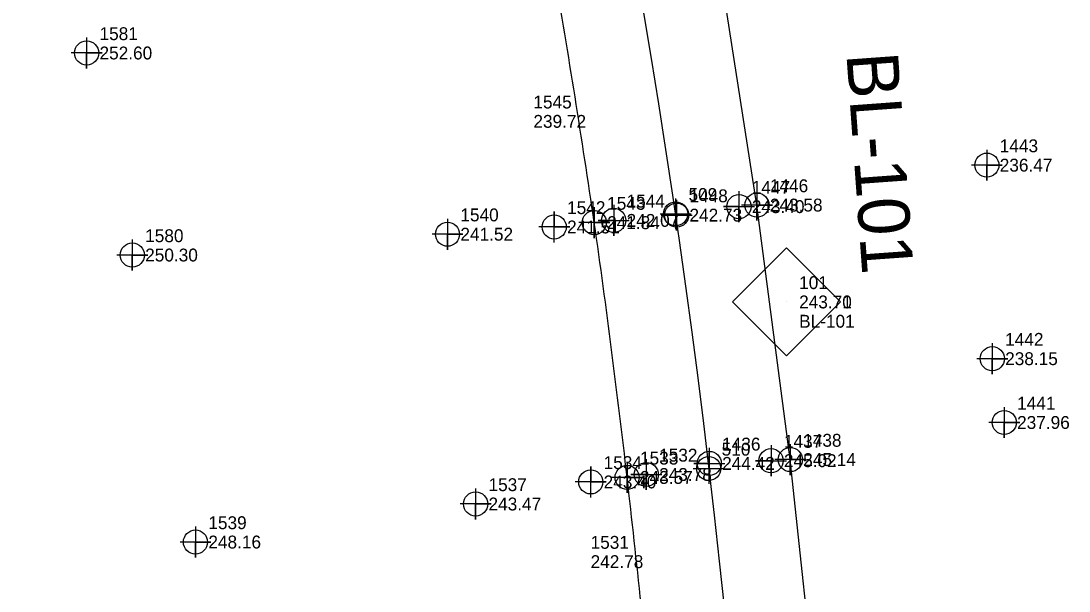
# Model space of a CAD drawing. Extents: x 2130621 to 2131998, y 642516 to 644503.
# Drawn here: x 2131091.5 to 2131294.9, y 643493.6 to 643604.3 of the extents above; entities that cross this region are included whole.
import ezdxf

# ---------------------------------------------------------------- set-up
doc = ezdxf.new("R2010")
doc.units = 0
for name, color, linetype in [('Cogo Default Point CELL', 7, 'Continuous'), ('COGO Default Point Number', 7, 'Continuous'), ('CTL Secondary Horizontal and Vertical CELL', 7, 'Continuous'), ('CTL Secondary Horizontal and Vertical Cogo Comment', 7, 'Continuous'), ('CTL Secondary Horizontal and Vertical Cogo Elevation', 7, 'Continuous'), ('CTL Secondary Horizontal and Vertical Cogo Number', 7, 'Continuous'), ('CTL Secondary Horizontal and Vertical Text', 7, 'Continuous'), ('Exist Other Culture Fence Line Cogo Elevation', 7, 'Continuous'), ('Exist Other Culture Fence Line Cogo Number', 7, 'Continuous'), ('Exist Other Culture Fence Line Cogo Point CELL', 7, 'Continuous'), ('Exist Other Culture Sign Cogo Elevation', 7, 'Continuous'), ('Exist Other Culture Sign Cogo Number', 7, 'Continuous'), ('Exist Roads EOP', 7, 'Continuous'), ('Exist Roads EOP Cogo Elevation', 7, 'Continuous'), ('Exist Roads EOP Cogo Number', 7, 'Continuous'), ('Exist Roads EOP Cogo Point CELL', 7, 'Continuous'), ('Exist Roads EOT Cogo Elevation', 7, 'Continuous'), ('Exist Roads EOT Cogo Number', 7, 'Continuous'), ('Exist Roads EOT Cogo Point CELL', 7, 'Continuous'), ('Exist Roads Soil Cogo Elevation', 7, 'Continuous'), ('Exist Roads Soil Cogo Number', 7, 'Continuous'), ('Exist Roads Soil Cogo Point CELL', 7, 'Continuous'), ('Exist Vegetation Woods Line Cogo Elevation', 7, 'Continuous'), ('Exist Vegetation Woods Line Cogo Number', 7, 'Continuous'), ('Exist Vegetation Woods Line Cogo Point CELL', 7, 'Continuous'), ('Prop Horizontal Alignment', 7, 'Continuous')]:
    doc.layers.add(name, color=color, linetype=linetype)

msp = doc.modelspace()

# ---------------------------------------------------------------- linework, layer by layer
at = {"layer": 'Cogo Default Point CELL'}
for points in [[(2131218.58, 643569.86), (2131218.58, 643566.86)], [(2131215.58, 643566.86), (2131218.58, 643566.86)], [(2131218.58, 643566.86), (2131221.58, 643566.86)], [(2131218.58, 643566.86), (2131218.58, 643563.86)], [(2131225.01, 643520.4), (2131225.01, 643517.4)], [(2131222.01, 643517.4), (2131225.01, 643517.4)], [(2131225.01, 643517.4), (2131228.01, 643517.4)], [(2131225.01, 643517.4), (2131225.01, 643514.4)]]:
    msp.add_lwpolyline(points, dxfattribs=at)
for centre in [(2131218.58, 643566.86), (2131225.01, 643517.4)]:
    msp.add_circle(centre, 2.34, dxfattribs=at)
at = {"layer": 'CTL Secondary Horizontal and Vertical CELL'}
msp.add_line((2131240.05, 643549.75), (2131240.05, 643549.75), dxfattribs=at)
msp.add_lwpolyline([(2131229.62, 643549.78), (2131240.1, 643560.27), (2131250.6, 643549.77), (2131240.12, 643539.28)], close=True, dxfattribs=at)
at = {"layer": 'Exist Other Culture Fence Line Cogo Point CELL'}
for points in [[(2131104.28, 643601.1), (2131104.28, 643595.1), (2131104.28, 643598.1), (2131107.28, 643598.1), (2131101.28, 643598.1)], [(2131113.14, 643561.86), (2131113.14, 643555.86), (2131113.14, 643558.86), (2131116.14, 643558.86), (2131110.14, 643558.86)], [(2131125.4, 643506.12), (2131125.4, 643500.12), (2131125.4, 643503.12), (2131128.4, 643503.12), (2131122.4, 643503.12)]]:
    msp.add_lwpolyline(points, dxfattribs=at)
for centre in [(2131104.28, 643598.1), (2131113.14, 643558.86), (2131125.4, 643503.12)]:
    msp.add_circle(centre, 2.34, dxfattribs=at)
at = {"layer": 'Exist Roads EOP'}
msp.add_lwpolyline([(2131264.27, 643222.56), (2131259.88, 643269.33), (2131257.02, 643319.4), (2131254.26, 643369.65), (2131250.08, 643419.42), (2131246.15, 643469.03), (2131240.84, 643519.13), (2131234.37, 643568.56), (2131226.33, 643620.18), (2131217.03, 643668.71), (2131205.62, 643717.61), (2131192.06, 643767.26), (2131177.97, 643815.09), (2131162.29, 643862.93), (2131145.36, 643910.85), (2131126.91, 643957.29), (2131112.37, 643996.12)], dxfattribs=at)
msp.add_spline([(2131166.25, 643216.7), (2131171.81, 643218.72), (2131182.37, 643223.97), (2131191.81, 643231.15), (2131200.5, 643239.7), (2131208.81, 643249.07), (2131216.07, 643259), (2131218.72, 643264.35), (2131220.54, 643270.1), (2131222.84, 643282.01), (2131224.36, 643293.92), (2131224.88, 643317.79), (2131222.06, 643367.67), (2131218.54, 643416.81), (2131214.32, 643466.35), (2131209.17, 643515.67), (2131202.79, 643565.15), (2131195.05, 643613.99), (2131186.4, 643662.48), (2131176.01, 643711.41), (2131164.62, 643759.89), (2131151.87, 643807.85), (2131137.86, 643855.41), (2131122.57, 643902.86), (2131105.96, 643949.49), (2131091.53, 643988.04)], degree=3, dxfattribs=at)
at = {"layer": 'Exist Roads EOP Cogo Point CELL'}
for points in [[(2131234.37, 643571.56), (2131234.37, 643565.56), (2131234.37, 643568.56), (2131237.37, 643568.56), (2131231.37, 643568.56)], [(2131202.79, 643568.15), (2131202.79, 643562.15), (2131202.79, 643565.15), (2131205.79, 643565.15), (2131199.79, 643565.15)], [(2131240.84, 643522.13), (2131240.84, 643516.13), (2131240.84, 643519.13), (2131243.84, 643519.13), (2131237.84, 643519.13)], [(2131209.17, 643518.67), (2131209.17, 643512.67), (2131209.17, 643515.67), (2131212.17, 643515.67), (2131206.17, 643515.67)]]:
    msp.add_lwpolyline(points, dxfattribs=at)
for centre in [(2131234.37, 643568.56), (2131202.79, 643565.15), (2131240.84, 643519.13), (2131209.17, 643515.67)]:
    msp.add_circle(centre, 2.34, dxfattribs=at)
at = {"layer": 'Exist Roads EOT Cogo Point CELL'}
for points in [[(2131230.87, 643571.26), (2131230.87, 643565.26), (2131230.87, 643568.26), (2131227.87, 643568.26), (2131233.87, 643568.26)], [(2131206.56, 643568.58), (2131206.56, 643562.58), (2131206.56, 643565.58), (2131203.56, 643565.58), (2131209.56, 643565.58)], [(2131218.77, 643569.61), (2131218.77, 643563.61), (2131218.77, 643566.61), (2131215.77, 643566.61), (2131221.77, 643566.61)], [(2131237.09, 643521.92), (2131237.09, 643515.92), (2131237.09, 643518.92), (2131234.09, 643518.92), (2131240.09, 643518.92)], [(2131225.11, 643521.39), (2131225.11, 643515.39), (2131225.11, 643518.39), (2131222.11, 643518.39), (2131228.11, 643518.39)], [(2131212.88, 643519.24), (2131212.88, 643513.24), (2131212.88, 643516.24), (2131209.88, 643516.24), (2131215.88, 643516.24)]]:
    msp.add_lwpolyline(points, dxfattribs=at)
for centre in [(2131230.87, 643568.26), (2131218.77, 643566.61), (2131206.56, 643565.58), (2131225.11, 643518.39), (2131237.09, 643518.92), (2131212.88, 643516.24)]:
    msp.add_circle(centre, 2.34, dxfattribs=at)
at = {"layer": 'Exist Roads Soil Cogo Point CELL'}
for points in [[(2131195.02, 643561.31), (2131195.02, 643567.31), (2131195.02, 643564.31), (2131198.02, 643564.31), (2131192.02, 643564.31)], [(2131202.11, 643511.79), (2131202.11, 643517.79), (2131202.11, 643514.79), (2131205.11, 643514.79), (2131199.11, 643514.79)]]:
    msp.add_lwpolyline(points, dxfattribs=at)
for centre in [(2131195.02, 643564.31), (2131202.11, 643514.79)]:
    msp.add_circle(centre, 2.34, dxfattribs=at)
at = {"layer": 'Exist Vegetation Woods Line Cogo Point CELL'}
for points in [[(2131278.98, 643579.32), (2131278.98, 643573.32), (2131278.98, 643576.32), (2131281.98, 643576.32), (2131275.98, 643576.32)], [(2131174.31, 643565.9), (2131174.31, 643559.9), (2131174.31, 643562.9), (2131177.31, 643562.9), (2131171.31, 643562.9)], [(2131280.03, 643541.73), (2131280.03, 643535.73), (2131280.03, 643538.73), (2131283.03, 643538.73), (2131277.03, 643538.73)], [(2131282.35, 643529.34), (2131282.35, 643523.34), (2131282.35, 643526.34), (2131285.35, 643526.34), (2131279.35, 643526.34)], [(2131179.77, 643513.51), (2131179.77, 643507.51), (2131179.77, 643510.51), (2131182.77, 643510.51), (2131176.77, 643510.51)]]:
    msp.add_lwpolyline(points, dxfattribs=at)
for centre in [(2131278.98, 643576.32), (2131174.31, 643562.9), (2131280.03, 643538.73), (2131282.35, 643526.34), (2131179.77, 643510.51)]:
    msp.add_circle(centre, 2.34, dxfattribs=at)
at = {"layer": 'Prop Horizontal Alignment'}
msp.add_arc((2129448.47, 643307.66), 1788.96, 4.14306, 22.49968, dxfattribs=at)

# ---------------------------------------------------------------- texts
at = {"layer": 'COGO Default Point Number'}
for s, p in [('509', (2131221.08, 643569.36)), ('510', (2131227.51, 643519.9))]:
    msp.add_text(s, height=2.5, dxfattribs=at).set_placement(p)
at = {"layer": 'CTL Secondary Horizontal and Vertical Cogo Comment'}
msp.add_text('BL-101', height=2.5, dxfattribs=at).set_placement((2131242.55, 643544.75))
msp.add_text('BL-101', height=2.5, dxfattribs=at).set_placement((2131242.55, 643544.75))
at = {"layer": 'CTL Secondary Horizontal and Vertical Cogo Elevation'}
for s in ['243.71', '243.70']:
    msp.add_text(s, height=2.5, dxfattribs=at).set_placement((2131242.55, 643548.5))
at = {"layer": 'CTL Secondary Horizontal and Vertical Cogo Number'}
msp.add_text('101', height=2.5, dxfattribs=at).set_placement((2131242.55, 643552.25))
msp.add_text('101', height=2.5, dxfattribs=at).set_placement((2131242.55, 643552.25))
at = {"layer": 'CTL Secondary Horizontal and Vertical Text'}
msp.add_text('BL-101', height=10, rotation=274.1431, dxfattribs=at).set_placement((2131251.71, 643597.91))
at = {"layer": 'Exist Other Culture Fence Line Cogo Elevation'}
for s, p in [('252.60', (2131106.78, 643596.85)), ('250.30', (2131115.64, 643557.61)), ('248.16', (2131127.9, 643501.87))]:
    msp.add_text(s, height=2.5, dxfattribs=at).set_placement(p)
at = {"layer": 'Exist Other Culture Fence Line Cogo Number'}
for s, p in [('1581', (2131106.78, 643600.6)), ('1580', (2131115.64, 643561.36)), ('1539', (2131127.9, 643505.62))]:
    msp.add_text(s, height=2.5, dxfattribs=at).set_placement(p)
at = {"layer": 'Exist Other Culture Sign Cogo Elevation'}
for s, p in [('239.72', (2131190.98, 643583.57)), ('242.78', (2131202.08, 643498.06))]:
    msp.add_text(s, height=2.5, dxfattribs=at).set_placement(p)
at = {"layer": 'Exist Other Culture Sign Cogo Number'}
for s, p in [('1545', (2131190.98, 643587.32)), ('1531', (2131202.08, 643501.81))]:
    msp.add_text(s, height=2.5, dxfattribs=at).set_placement(p)
at = {"layer": 'Exist Roads EOP Cogo Elevation'}
for s, p in [('243.58', (2131236.87, 643567.31)), ('241.84', (2131205.29, 643563.9)), ('245.14', (2131243.34, 643517.88)), ('243.57', (2131211.67, 643514.42))]:
    msp.add_text(s, height=2.5, dxfattribs=at).set_placement(p)
at = {"layer": 'Exist Roads EOP Cogo Number'}
for s, p in [('1446', (2131236.87, 643571.06)), ('1543', (2131205.29, 643567.65)), ('1438', (2131243.34, 643521.63)), ('1533', (2131211.67, 643518.17))]:
    msp.add_text(s, height=2.5, dxfattribs=at).set_placement(p)
at = {"layer": 'Exist Roads EOT Cogo Elevation'}
for s, p in [('243.40', (2131233.37, 643567.01)), ('242.07', (2131209.06, 643564.33)), ('242.73', (2131221.27, 643565.36)), ('244.42', (2131227.61, 643517.14)), ('245.02', (2131239.59, 643517.67)), ('243.78', (2131215.38, 643514.99))]:
    msp.add_text(s, height=2.5, dxfattribs=at).set_placement(p)
at = {"layer": 'Exist Roads EOT Cogo Number'}
for s, p in [('1447', (2131233.37, 643570.76)), ('1544', (2131209.06, 643568.08)), ('1448', (2131221.27, 643569.11)), ('1437', (2131239.59, 643521.42)), ('1436', (2131227.61, 643520.89)), ('1532', (2131215.38, 643518.74))]:
    msp.add_text(s, height=2.5, dxfattribs=at).set_placement(p)
at = {"layer": 'Exist Roads Soil Cogo Elevation'}
for s, p in [('241.51', (2131197.52, 643563.06)), ('243.40', (2131204.61, 643513.54))]:
    msp.add_text(s, height=2.5, dxfattribs=at).set_placement(p)
at = {"layer": 'Exist Roads Soil Cogo Number'}
for s, p in [('1542', (2131197.52, 643566.81)), ('1534', (2131204.61, 643517.29))]:
    msp.add_text(s, height=2.5, dxfattribs=at).set_placement(p)
at = {"layer": 'Exist Vegetation Woods Line Cogo Elevation'}
for s, p in [('236.47', (2131281.48, 643575.07)), ('241.52', (2131176.81, 643561.65)), ('238.15', (2131282.53, 643537.48)), ('237.96', (2131284.85, 643525.09)), ('243.47', (2131182.27, 643509.26))]:
    msp.add_text(s, height=2.5, dxfattribs=at).set_placement(p)
at = {"layer": 'Exist Vegetation Woods Line Cogo Number'}
for s, p in [('1443', (2131281.48, 643578.82)), ('1540', (2131176.81, 643565.4)), ('1442', (2131282.53, 643541.23)), ('1441', (2131284.85, 643528.84)), ('1537', (2131182.27, 643513.01))]:
    msp.add_text(s, height=2.5, dxfattribs=at).set_placement(p)

doc.saveas('drawing.dxf')
